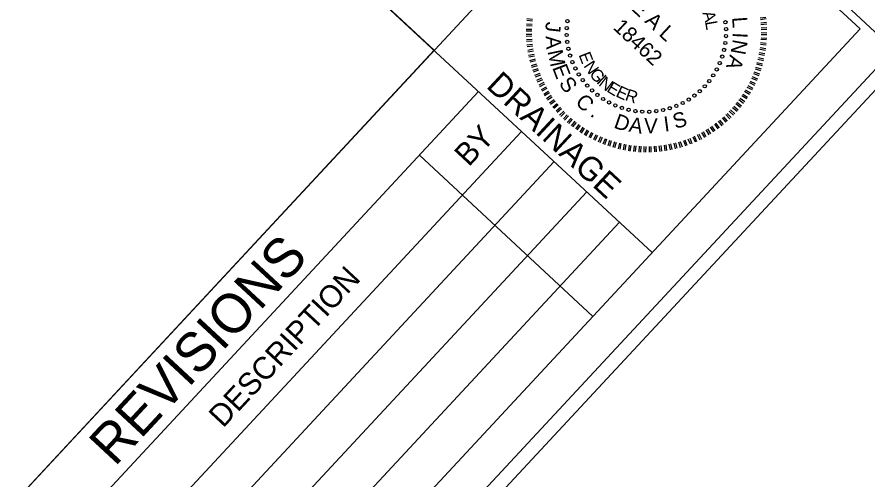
# Model space of a CAD drawing. Extents: x 2057696 to 2061410, y 685900 to 689434.
# Drawn here: x 2059039.7 to 2059259, y 688396.4 to 688515.7 of the extents above; entities that cross this region are included whole.
import ezdxf

# ---------------------------------------------------------------- set-up
doc = ezdxf.new("R2010")
doc.units = 0
for name, color, linetype in [('Default', 7, 'Continuous'), ('Exist Vertical Profile Vertical Axis Label', 7, 'Continuous'), ('Prop Vertical Profile Curve Label', 7, 'Continuous')]:
    doc.layers.add(name, color=color, linetype=linetype)

msp = doc.modelspace()

# ---------------------------------------------------------------- linework, layer by layer
at = {"layer": 'Default'}
for p, q in [((2059256.98, 688512.7), (2058378.02, 689329.67)), ((2059200.86, 688564.86), (2058628.8, 687949.39)), ((2059089.03, 688561.28), (2059203.36, 688455.01)), ((2059256.98, 688512.7), (2058684.92, 687897.23)), ((2059020.9, 688348.34), (2059158.64, 688496.53)), ((2059031.98, 688338.09), (2059169.69, 688486.26)), ((2059143.41, 688480.15), (2059188.03, 688438.63)), ((2059040.37, 688330.29), (2059178.11, 688478.49)), ((2059048.78, 688322.47), (2059186.52, 688470.66)), ((2059057.2, 688314.65), (2059194.94, 688462.84))]:
    msp.add_line(p, q, dxfattribs=at)
for points in [[(2057696.33, 688791.9), (2058682.81, 687874.99), (2059279.2, 688516.63), (2058292.71, 689433.54)], [(2057714.84, 688796.54), (2058691.07, 687889.16), (2059265.67, 688507.36), (2058289.44, 689414.74)]]:
    msp.add_lwpolyline(points, close=True, dxfattribs=at)
at = {"layer": 'Exist Vertical Profile Vertical Axis Label'}
for p, q in [((2059172.44, 688513.83), (2059170.98, 688513.91)), ((2059172.52, 688514.68), (2059171.06, 688514.81)), ((2059172.56, 688515.11), (2059171.09, 688515.24)), ((2059231.24, 688515.55), (2059232.69, 688515.74)), ((2059231.28, 688515.1), (2059232.76, 688515.32)), ((2059231.34, 688514.28), (2059232.82, 688514.39)), ((2059231.38, 688513.83), (2059232.89, 688513.97)), ((2059172.4, 688512.07), (2059170.91, 688512.13)), ((2059172.41, 688512.53), (2059170.95, 688512.55)), ((2059172.43, 688513.38), (2059170.97, 688513.46)), ((2059231.45, 688512.54), (2059232.91, 688512.61)), ((2059231.46, 688512.99), (2059232.92, 688513.07)), ((2059231.46, 688511.71), (2059232.92, 688511.69)), ((2059172.41, 688511.25), (2059170.92, 688511.2)), ((2059172.4, 688510.8), (2059170.96, 688510.75)), ((2059172.45, 688509.98), (2059171, 688509.85)), ((2059172.5, 688509.53), (2059171.04, 688509.4)), ((2059231.39, 688509.99), (2059232.85, 688509.91)), ((2059231.43, 688510.41), (2059232.89, 688510.33)), ((2059231.45, 688511.26), (2059232.93, 688511.26)), ((2059172.58, 688508.68), (2059171.13, 688508.5)), ((2059172.62, 688508.24), (2059171.17, 688508.05)), ((2059172.73, 688507.42), (2059171.31, 688507.15)), ((2059231.11, 688507.43), (2059232.6, 688507.22)), ((2059231.2, 688507.86), (2059232.64, 688507.64)), ((2059231.28, 688508.71), (2059232.77, 688508.55)), ((2059231.31, 688509.13), (2059232.78, 688509)), ((2059172.83, 688506.97), (2059171.35, 688506.7)), ((2059172.96, 688506.12), (2059171.52, 688505.83)), ((2059173.06, 688505.68), (2059171.61, 688505.39)), ((2059230.74, 688505.32), (2059232.16, 688504.97)), ((2059230.89, 688506.15), (2059232.33, 688505.88)), ((2059230.98, 688506.57), (2059232.43, 688506.31)), ((2059173.25, 688504.89), (2059171.8, 688504.49)), ((2059173.34, 688504.44), (2059171.93, 688504.07)), ((2059173.56, 688503.63), (2059172.17, 688503.18)), ((2059173.71, 688503.18), (2059172.29, 688502.76)), ((2059230.03, 688502.85), (2059231.43, 688502.37)), ((2059230.27, 688503.66), (2059231.69, 688503.26)), ((2059230.38, 688504.06), (2059231.83, 688503.69)), ((2059230.62, 688504.86), (2059232.04, 688504.57)), ((2059173.95, 688502.39), (2059172.59, 688501.92)), ((2059174.1, 688502), (2059172.71, 688501.5)), ((2059174.42, 688501.19), (2059173.03, 688500.63)), ((2059174.59, 688500.77), (2059173.21, 688500.22)), ((2059229.45, 688501.18), (2059230.83, 688500.68)), ((2059229.6, 688501.61), (2059231, 688501.08)), ((2059229.89, 688502.42), (2059231.31, 688501.97)), ((2059174.89, 688499.99), (2059173.56, 688499.38)), ((2059175.09, 688499.59), (2059173.73, 688498.96)), ((2059175.46, 688498.84), (2059174.16, 688498.15)), ((2059175.63, 688498.42), (2059174.33, 688497.74)), ((2059228.42, 688498.86), (2059229.75, 688498.2)), ((2059228.62, 688499.24), (2059229.92, 688498.6)), ((2059228.97, 688500), (2059230.34, 688499.44)), ((2059229.14, 688500.4), (2059230.51, 688499.84)), ((2059176.03, 688497.69), (2059174.76, 688496.98)), ((2059176.26, 688497.28), (2059174.96, 688496.59)), ((2059176.68, 688496.58), (2059175.44, 688495.79)), ((2059176.91, 688496.21), (2059175.66, 688495.42)), ((2059227.18, 688496.59), (2059228.43, 688495.84)), ((2059227.38, 688496.97), (2059228.68, 688496.22)), ((2059227.8, 688497.7), (2059229.13, 688497.03)), ((2059228.03, 688498.11), (2059229.33, 688497.41)), ((2059177.36, 688495.49), (2059176.17, 688494.65)), ((2059177.64, 688495.12), (2059176.4, 688494.28)), ((2059178.12, 688494.43), (2059176.93, 688493.53)), ((2059178.39, 688494.06), (2059177.21, 688493.17)), ((2059225.75, 688494.44), (2059226.95, 688493.58)), ((2059226.03, 688494.8), (2059227.23, 688493.94)), ((2059226.48, 688495.5), (2059227.73, 688494.7)), ((2059226.73, 688495.88), (2059227.98, 688495.08)), ((2059178.9, 688493.39), (2059177.76, 688492.45)), ((2059179.17, 688493.08), (2059178.04, 688492.14)), ((2059179.73, 688492.41), (2059178.62, 688491.44)), ((2059180.03, 688492.08), (2059178.93, 688491.11)), ((2059224.12, 688492.42), (2059225.25, 688491.48)), ((2059224.4, 688492.77), (2059225.55, 688491.81)), ((2059224.96, 688493.43), (2059226.14, 688492.49)), ((2059225.21, 688493.76), (2059226.39, 688492.87)), ((2059180.59, 688491.46), (2059179.54, 688490.44)), ((2059180.92, 688491.16), (2059179.86, 688490.14)), ((2059181.49, 688490.57), (2059180.5, 688489.5)), ((2059181.82, 688490.26), (2059180.83, 688489.19)), ((2059182.48, 688489.7), (2059181.51, 688488.55)), ((2059221.41, 688489.72), (2059222.38, 688488.61)), ((2059221.72, 688490), (2059222.71, 688488.92)), ((2059222.36, 688490.58), (2059223.38, 688489.53)), ((2059222.67, 688490.91), (2059223.71, 688489.83)), ((2059223.25, 688491.48), (2059224.35, 688490.46)), ((2059223.56, 688491.81), (2059224.66, 688490.79)), ((2059182.78, 688489.42), (2059181.84, 688488.3)), ((2059183.44, 688488.86), (2059182.53, 688487.71)), ((2059183.8, 688488.58), (2059182.88, 688487.43)), ((2059184.45, 688488.08), (2059183.59, 688486.88)), ((2059184.83, 688487.82), (2059183.97, 688486.63)), ((2059218.7, 688487.58), (2059219.54, 688486.39)), ((2059219.4, 688488.11), (2059220.29, 688486.92)), ((2059219.73, 688488.36), (2059220.63, 688487.17)), ((2059220.41, 688488.86), (2059221.35, 688487.73)), ((2059220.77, 688489.14), (2059221.71, 688488)), ((2059185.51, 688487.34), (2059184.71, 688486.09)), ((2059185.89, 688487.09), (2059185.09, 688485.84)), ((2059186.6, 688486.64), (2059185.88, 688485.37)), ((2059187.01, 688486.42), (2059186.23, 688485.14)), ((2059187.74, 688485.99), (2059187.04, 688484.69)), ((2059188.12, 688485.79), (2059187.42, 688484.5)), ((2059188.87, 688485.4), (2059188.23, 688484.05)), ((2059215.01, 688485.42), (2059215.67, 688484.1)), ((2059215.4, 688485.62), (2059216.06, 688484.3)), ((2059216.13, 688486.02), (2059216.87, 688484.72)), ((2059216.52, 688486.22), (2059217.23, 688484.95)), ((2059217.25, 688486.67), (2059218.01, 688485.4)), ((2059217.61, 688486.9), (2059218.43, 688485.63)), ((2059218.34, 688487.35), (2059219.18, 688486.11)), ((2059189.28, 688485.23), (2059188.64, 688483.88)), ((2059190.03, 688484.88), (2059189.47, 688483.51)), ((2059190.47, 688484.69), (2059189.88, 688483.34)), ((2059191.25, 688484.37), (2059190.71, 688482.97)), ((2059191.62, 688484.22), (2059191.14, 688482.83)), ((2059192.43, 688483.94), (2059191.98, 688482.51)), ((2059192.86, 688483.79), (2059192.38, 688482.39)), ((2059193.67, 688483.56), (2059193.27, 688482.14)), ((2059194.09, 688483.41), (2059193.7, 688481.99)), ((2059194.93, 688483.2), (2059194.58, 688481.79)), ((2059195.35, 688483.11), (2059195.03, 688481.67)), ((2059208.96, 688483.21), (2059209.33, 688481.79)), ((2059209.38, 688483.33), (2059209.75, 688481.92)), ((2059210.2, 688483.55), (2059210.62, 688482.13)), ((2059210.62, 688483.67), (2059211.07, 688482.28)), ((2059211.43, 688483.94), (2059211.93, 688482.55)), ((2059211.82, 688484.09), (2059212.32, 688482.7)), ((2059212.61, 688484.38), (2059213.19, 688483.02)), ((2059213.05, 688484.53), (2059213.58, 688483.17)), ((2059213.84, 688484.88), (2059214.44, 688483.55)), ((2059214.23, 688485.08), (2059214.84, 688483.69)), ((2059196.16, 688482.93), (2059195.89, 688481.49)), ((2059196.61, 688482.87), (2059196.32, 688481.4)), ((2059197.44, 688482.71), (2059197.25, 688481.25)), ((2059197.89, 688482.65), (2059197.65, 688481.18)), ((2059198.72, 688482.55), (2059198.59, 688481.08)), ((2059199.14, 688482.51), (2059199.01, 688481.05)), ((2059200, 688482.43), (2059199.94, 688480.95)), ((2059200.45, 688482.42), (2059200.37, 688480.91)), ((2059201.27, 688482.37), (2059201.27, 688480.89)), ((2059201.72, 688482.36), (2059201.7, 688480.9)), ((2059202.6, 688482.37), (2059202.62, 688480.91)), ((2059203.02, 688482.39), (2059203.08, 688480.9)), ((2059203.87, 688482.42), (2059204, 688480.96)), ((2059204.32, 688482.46), (2059204.43, 688480.98)), ((2059205.14, 688482.57), (2059205.33, 688481.06)), ((2059205.59, 688482.61), (2059205.75, 688481.13)), ((2059206.43, 688482.7), (2059206.67, 688481.25)), ((2059206.86, 688482.76), (2059207.09, 688481.31)), ((2059207.7, 688482.95), (2059208.02, 688481.48)), ((2059208.12, 688483.02), (2059208.44, 688481.6))]:
    msp.add_line(p, q, dxfattribs=at)
for centre in [(2059181.54, 688514.68), (2059222.27, 688514.4), (2059181.37, 688512.9), (2059222.41, 688512.62), (2059181.35, 688511.11), (2059181.5, 688509.32), (2059222.23, 688509.04), (2059222.4, 688510.82), (2059181.8, 688507.55), (2059221.91, 688507.28), (2059182.25, 688505.82), (2059221.43, 688505.55), (2059182.85, 688504.13), (2059183.6, 688502.5), (2059220.81, 688503.87), (2059184.48, 688500.94), (2059219.13, 688500.71), (2059220.04, 688502.25), (2059185.5, 688499.47), (2059186.64, 688498.09), (2059218.09, 688499.24), (2059187.9, 688496.81), (2059215.66, 688496.62), (2059216.93, 688497.88), (2059189.26, 688495.65), (2059190.73, 688494.61), (2059192.27, 688493.71), (2059212.8, 688494.46), (2059214.27, 688495.48), (2059193.89, 688492.94), (2059195.57, 688492.31), (2059197.3, 688491.84), (2059199.06, 688491.51), (2059204.42, 688491.48), (2059206.19, 688491.78), (2059207.92, 688492.23), (2059209.61, 688492.83), (2059211.24, 688493.58), (2059200.84, 688491.35), (2059202.64, 688491.33)]:
    msp.add_circle(centre, 0.425, dxfattribs=at)
at = {"layer": 'Prop Vertical Profile Curve Label'}
msp.add_lwpolyline([(2058210.31, 688884.84), (2058901.31, 688242.58), (2059147.24, 688507.17), (2059089.03, 688561.28), (2059142.65, 688618.97), (2058378.02, 689329.67), (2058078.47, 689007.38), (2058137.07, 688952.92)], dxfattribs=at)

# ---------------------------------------------------------------- texts
at = {"layer": 'Default'}
for s, height, rotation, p in [('DRAINAGE', 6.129, 317.0934, (2059160.38, 688497.7)), ('BY', 5.746, 47.0934, (2059156.13, 688476.96)), ('REVISIONS', 10.113, 47.0934, (2059064.94, 688399.66)), ('DESCRIPTION', 5.746, 47.0934, (2059092.83, 688409.64))]:
    msp.add_text(s, height=height, rotation=rotation, dxfattribs=at).set_placement(p)
at = {"layer": 'Exist Vertical Profile Vertical Axis Label'}
for s, height, rotation, p in [('S E A L', 3.898, 317.0934, (2059194.08, 688521.21)), ('A', 3.11, 285.8406, (2059216.3, 688516.84)), ('J', 3.9, 263.8779, (2059176.07, 688514.6)), ('18462', 3.898, 317.0934, (2059193.1, 688512.81)), ('L', 3.12, 279.6567, (2059217, 688514.5)), ('L', 3.88, 274.3192, (2059223.96, 688515.66)), ('A', 3.9, 272.8779, (2059175.95, 688510.81)), ('N', 3.88, 259.7882, (2059224.22, 688510.15)), ('I', 3.88, 267.0537, (2059224.18, 688511.82)), ('M', 3.9, 281.8779, (2059176.4, 688506.89)), ('E', 3.12, 291.3578, (2059184.38, 688506.01)), ('A', 3.88, 252.5227, (2059223.43, 688506.17)), ('E', 3.9, 290.8779, (2059177.59, 688502.71)), ('N', 3.12, 303.7256, (2059185.6, 688503.14)), ('G', 3.12, 309.9095, (2059187.03, 688500.93)), ('I', 3.11, 316.0934, (2059188.88, 688498.91)), ('S', 3.9, 305.8093, (2059179.18, 688498.6)), ('N', 3.11, 322.2774, (2059189.39, 688498.23)), ('E', 3.12, 328.4613, (2059191.46, 688496.66)), ('E', 3.12, 334.6452, (2059193.79, 688495.37)), ('R', 3.12, 340.8291, (2059196.19, 688494.37)), ('C', 3.9, 314.7574, (2059183.37, 688493.63)), ('.', 3.9, 323.7574, (2059187.21, 688490.38)), ('D', 3.9, 340.8048, (2059193.27, 688487.27)), ('A', 3.9, 349.8048, (2059197.2, 688486.23)), ('V', 3.9, 358.8048, (2059201.26, 688485.8)), ('I', 3.9, 7.8048, (2059206.63, 688486.16)), ('S', 3.9, 16.8048, (2059209.36, 688486.85))]:
    msp.add_text(s, height=height, rotation=rotation, dxfattribs=at).set_placement(p)

doc.saveas('drawing.dxf')
